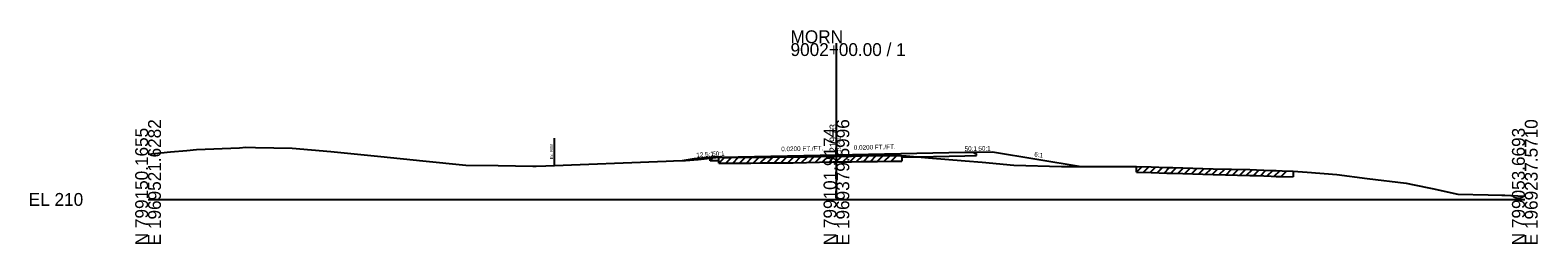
# Model space of a CAD drawing. Extents: x -26 to 2313, y -1511 to 5559.
# Drawn here: x -25.7 to 302.8, y 490.3 to 536.9 of the extents above; entities that cross this region are included whole.
import ezdxf

# ---------------------------------------------------------------- set-up
doc = ezdxf.new("R2010")
doc.units = 0
for name, color, linetype in [('Default', 7, 'Continuous'), ('RD_XS_Base', 7, 'Continuous'), ('RD_XS_EarthShd', 7, 'Continuous'), ('RD_XS_ExGround', 7, 'Continuous'), ('RD_XS_ExPaveRet', 7, 'Continuous'), ('RD_XS_ExRW', 7, 'Continuous'), ('RD_XS_Misc_Line', 7, 'Continuous'), ('RD_XS_Pave', 7, 'Continuous'), ('RD_XS_PaveShd', 7, 'Continuous'), ('RD_XS_TieSlope', 7, 'Continuous'), ('RD_XS_TX_Elev_EX', 7, 'Continuous'), ('RD_XS_TX_Elev_PR', 7, 'Continuous'), ('RD_XS_TX_Profile', 7, 'Continuous'), ('RD_XS_TX_ShdSlope', 7, 'Continuous'), ('RD_XS_TX_Slope', 7, 'Continuous')]:
    doc.layers.add(name, color=color, linetype=linetype)

msp = doc.modelspace()

# ---------------------------------------------------------------- linework, layer by layer
at = {"layer": 'Default'}
for p, q in [((150, 500), (150, 534.07)), ((0, 500), (150, 500)), ((150, 500), (300, 500))]:
    msp.add_line(p, q, dxfattribs=at)
at = {"layer": 'RD_XS_Base'}
for p, q in [((164.23, 509.24), (164.23, 509.58)), ((178, 509.51), (180.5, 509.56)), ((180, 510.03), (180, 510.33)), ((180.5, 510.04), (180, 510.03)), ((180.5, 509.56), (180.5, 510.04)), ((122.5, 508.88), (123, 508.89)), ((122.5, 508.4), (122.5, 508.88)), ((124.4, 508.44), (122.5, 508.4)), ((123, 508.89), (123, 509.19)), ((124.4, 508.44), (124.4, 509.19))]:
    msp.add_line(p, q, dxfattribs=at)
at = {"layer": 'RD_XS_EarthShd'}
for p, q in [((180, 510.33), (184, 510.41)), ((123, 509.19), (119, 508.87))]:
    msp.add_line(p, q, dxfattribs=at)
at = {"layer": 'RD_XS_ExGround'}
msp.add_lwpolyline([(0, 509.88), (4.88, 510.34), (8.46, 510.69), (10.58, 510.92), (19.94, 511.25), (21.32, 511.36), (23.39, 511.34), (31.42, 511.16), (39.81, 510.46), (50.72, 509.39), (59.86, 508.41), (69.25, 507.47), (76.28, 507.41), (83.83, 507.25), (84.56, 507.24), (86.65, 507.32), (112.87, 508.33), (114.48, 508.4), (117.12, 508.49), (119.84, 508.68), (124.4, 509.19), (125.3, 509.15), (126.9, 509.16), (131.36, 509.19), (133.5, 509.22), (135.97, 509.24), (136.44, 509.25), (140.6, 509.23), (149.19, 509.41), (150, 509.41), (151.24, 509.42), (152.54, 509.43), (153.28, 509.45), (155.36, 509.53), (157.21, 509.54), (158.97, 509.55), (162.22, 509.61), (164.23, 509.58), (165.21, 509.48), (170.05, 509.1), (178.06, 508.39), (181.79, 508.14), (188.67, 507.49), (199.02, 507.18), (215.39, 507.21), (218.57, 507.11), (222.03, 506.98), (223.32, 506.96), (229.85, 506.73), (232.1, 506.7), (240.05, 506.5), (241.5, 506.45), (244.7, 506.32), (245.83, 506.27), (247.11, 506.22), (249.5, 506.15), (252.59, 505.93), (259.05, 505.42), (265.67, 504.58), (274.12, 503.51), (275.92, 503.19), (279.83, 502.37), (285.38, 501.14), (292.05, 500.99), (294.97, 500.93), (295.64, 500.92), (296.98, 500.87), (300, 500.71)], dxfattribs=at)
at = {"layer": 'RD_XS_ExPaveRet'}
for p, q in [((164.23, 509.58), (164.23, 508.33)), ((124.4, 507.94), (124.4, 509.19)), ((124.4, 507.94), (125.3, 507.9)), ((125.3, 507.9), (126.9, 507.91)), ((126.9, 507.91), (131.36, 507.94)), ((131.36, 507.94), (133.5, 507.97)), ((133.5, 507.97), (135.97, 507.99)), ((135.97, 507.99), (136.44, 508)), ((136.44, 508), (140.6, 507.98)), ((140.6, 507.98), (149.19, 508.16)), ((149.19, 508.16), (150, 508.16)), ((150, 508.16), (151.24, 508.17)), ((151.24, 508.17), (152.54, 508.18)), ((152.54, 508.18), (153.28, 508.2)), ((153.28, 508.2), (155.36, 508.28)), ((155.36, 508.28), (157.21, 508.29)), ((157.21, 508.29), (158.97, 508.3)), ((158.97, 508.3), (162.22, 508.36)), ((162.22, 508.36), (164.23, 508.33)), ((215.39, 505.96), (215.39, 507.21)), ((215.39, 505.96), (218.57, 505.86)), ((249.5, 506.15), (249.5, 504.9)), ((218.57, 505.86), (222.03, 505.73)), ((222.03, 505.73), (223.32, 505.71)), ((223.32, 505.71), (229.85, 505.48)), ((229.85, 505.48), (232.1, 505.45)), ((232.1, 505.45), (240.05, 505.25)), ((240.05, 505.25), (241.5, 505.2)), ((241.5, 505.2), (244.7, 505.07)), ((244.7, 505.07), (245.83, 505.02)), ((245.83, 505.02), (247.11, 504.97)), ((247.11, 504.97), (249.5, 504.9))]:
    msp.add_line(p, q, dxfattribs=at)
at = {"layer": 'RD_XS_ExRW'}
msp.add_line((88.5, 513.39), (88.5, 507.39), dxfattribs=at)
at = {"layer": 'RD_XS_Misc_Line'}
for p, q in [((133.4, 507.97), (134.66, 509.23)), ((134.9, 507.98), (136.16, 509.24)), ((136.4, 508), (137.65, 509.24)), ((137.9, 507.99), (139.15, 509.24)), ((139.4, 507.99), (140.65, 509.23)), ((140.9, 507.99), (142.18, 509.26)), ((142.4, 508.02), (143.68, 509.3)), ((143.9, 508.05), (145.18, 509.33)), ((145.4, 508.08), (146.68, 509.36)), ((146.9, 508.11), (148.18, 509.39)), ((148.4, 508.14), (149.67, 509.41)), ((149.9, 508.16), (151.16, 509.42)), ((151.4, 508.17), (152.67, 509.43)), ((152.9, 508.19), (154.2, 509.49)), ((154.4, 508.24), (155.69, 509.53)), ((155.9, 508.28), (157.16, 509.54)), ((157.4, 508.29), (158.66, 509.55)), ((158.9, 508.3), (160.18, 509.57)), ((160.4, 508.32), (161.68, 509.6)), ((161.9, 508.35), (163.15, 509.6)), ((124.4, 507.94), (125.61, 509.15)), ((125.9, 507.91), (127.16, 509.17)), ((127.4, 507.92), (128.66, 509.18)), ((128.9, 507.93), (130.16, 509.19)), ((130.4, 507.94), (131.66, 509.2)), ((131.9, 507.95), (133.17, 509.22)), ((215.39, 505.96), (216.6, 507.17)), ((216.89, 505.91), (218.1, 507.13)), ((218.39, 505.87), (219.59, 507.07)), ((219.89, 505.81), (221.09, 507.02)), ((221.39, 505.76), (222.6, 506.97)), ((222.89, 505.72), (224.1, 506.93)), ((224.39, 505.67), (225.59, 506.88)), ((225.89, 505.62), (227.09, 506.83)), ((227.39, 505.57), (228.59, 506.78)), ((228.89, 505.52), (230.1, 506.73)), ((230.39, 505.47), (231.62, 506.7)), ((231.89, 505.45), (233.11, 506.67)), ((233.39, 505.41), (234.61, 506.63)), ((234.89, 505.38), (236.11, 506.6)), ((236.39, 505.34), (237.61, 506.56)), ((237.89, 505.3), (239.11, 506.52)), ((239.39, 505.27), (240.6, 506.48)), ((240.89, 505.22), (242.1, 506.43)), ((242.39, 505.17), (243.59, 506.37)), ((243.89, 505.11), (245.09, 506.31)), ((245.39, 505.04), (246.59, 506.24)), ((246.89, 504.98), (248.1, 506.19))]:
    msp.add_line(p, q, dxfattribs=at)
at = {"layer": 'RD_XS_Pave'}
for p, q in [((125, 509.23), (150, 509.73)), ((150, 509.73), (178, 510.29)), ((164.23, 509.24), (178, 509.51))]:
    msp.add_line(p, q, dxfattribs=at)
at = {"layer": 'RD_XS_PaveShd'}
for p, q in [((125, 509.23), (123, 509.19)), ((178, 510.29), (180, 510.33))]:
    msp.add_line(p, q, dxfattribs=at)
at = {"layer": 'RD_XS_TieSlope'}
for p, q in [((184, 510.41), (203.33, 507.19)), ((119, 508.87), (116.41, 508.44))]:
    msp.add_line(p, q, dxfattribs=at)

# ---------------------------------------------------------------- texts
at = {"layer": 'Default'}
for s, p in [('MORN', (140, 534.07)), ('9002+00.00 / 1', (140, 531.27)), ('EL 210', (-26, 498.6))]:
    msp.add_text(s, height=2.8, dxfattribs=at).set_placement(p)
for s, p in [('E 1969521.6282', (2.8, 490)), ('E 1969379.5996', (152.8, 490)), ('E 1969237.5710', (302.8, 490)), ('N 799150.1655', (0, 490)), ('N 799101.9174', (150, 490)), ('N 799053.6693', (300, 490))]:
    msp.add_text(s, height=2.8, rotation=90, dxfattribs=at).set_placement(p)
at = {"layer": 'RD_XS_ExRW'}
msp.add_text('Ex. R/W ', height=0.65, rotation=90, dxfattribs=at).set_placement((88.25, 508.77))
at = {"layer": 'RD_XS_TX_Elev_EX'}
msp.add_text('219.41', height=1, rotation=90, dxfattribs=at).set_placement((151.01, 509.41))
at = {"layer": 'RD_XS_TX_Elev_PR'}
msp.add_text(' 219.73', height=1.5, rotation=90, dxfattribs=at).set_placement((150, 509.73))
at = {"layer": 'RD_XS_TX_Profile'}
for p in [(122.94, 509.44), (177.94, 510.54)]:
    msp.add_text('50:1', height=1, rotation=1.1458, dxfattribs=at).set_placement(p)
at = {"layer": 'RD_XS_TX_ShdSlope'}
for s, rotation, p in [('12.5:1', 4.5739, (119.5, 509.16)), ('50:1', 1.1458, (180.94, 510.6))]:
    msp.add_text(s, height=1, rotation=rotation, dxfattribs=at).set_placement(p)
at = {"layer": 'RD_XS_TX_Slope'}
for s, rotation, p in [('0.0200 FT./FT.', 1.1458, (137.98, 510.49)), ('0.0200 FT./FT.', 1.1458, (153.79, 510.81)), ('6:1', 350.5377, (193.05, 509.41))]:
    msp.add_text(s, height=1, rotation=rotation, dxfattribs=at).set_placement(p)

doc.saveas('drawing.dxf')
